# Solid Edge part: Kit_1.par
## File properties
Sűrűség: 0,000 kg/m^3
Pontosság: 0,990
Author: ahadarics
Last saved by: psaghy
Revision: 77
Username: ahadarics
Dokumentum tartalom típus: 0
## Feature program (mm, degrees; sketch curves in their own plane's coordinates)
base feature "unnamed BaseFeature 1"
sketch for "Furat_1" plane through (0, 0, 39) normal (0, 0, 1) x-axis (0, -1, 0)
  hole centre (-23.25, 23.25) bore radius 3.3235
hole "Furat_1" nominal diameter 8 finite  VBottomAngle = 118 deg; ThreadDepth = 16 mm
sketch for "unnamed Hole 1" plane through (0, 0, 39) normal (0, 0, 1) x-axis (0, -1, 0)
  hole centre (-23.25, -23.25) bore radius 3.3235
hole "unnamed Hole 1" finite
sketch for "unnamed Hole 2" plane through (0, 0, 39) normal (0, 0, 1) x-axis (0, -1, 0)
  hole centre (23.25, -23.25) bore radius 3.3235
hole "unnamed Hole 2" finite
sketch for "unnamed Hole 3" plane through (0, 0, 39) normal (0, 0, 1) x-axis (0, -1, 0)
  hole centre (23.25, 23.25) bore radius 3.3235
hole "unnamed Hole 3" finite
pattern "unnamed Pattern 1" of "Furat_1", "unnamed Hole 1", "unnamed Hole 2", "unnamed Hole 3"
sketch for "Furat_5" plane through (32.5, 0.0003, 21.2488) normal (1, 0, 0) x-axis (0, 0, -1)
hole "Furat_5" diameter 13.157 finite  ThreadDepth = 10 mm
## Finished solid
Body 1: solid body, 446 faces, 1036 edges, 651 vertices, 7 internal voids.
  Faces by surface: plane 155, cylinder 135, torus 52, cone 51, sphere 23, spline 21, swept 9
  Edges by curve: line 368, circle 356, curve on surface 286, spline 26
Bounding box of the edges (mm; curved faces can reach further): 65.000 x 65.000 x 56.500, from (-32.5, -32.5, 8) to (32.5002, 32.5, 64.5).
Cylindrical faces by radius (mm): R0.3125 x1, R0.3838 x1, R0.4089 x1, R0.4253 x1, R0.4408 x1, R0.5 x8, R0.5003 x1, R0.5483 x1, R0.5961 x1, R0.615 x1, R0.6311 x1, R0.6362 x1, R0.652 x1, R0.6792 x1, R0.73 x1, R0.7378 x1, R0.7396 x1, R0.9114 x1, R1 x20, R1.0004 x7, R1.001 x6, R1.0014 x8, R1.0015 x1, R1.0026 x1, R1.0394 x1, R1.0539 x1, R1.0734 x1, R1.0987 x1, R1.1871 x1, R1.2561 x1, R1.2722 x2, R1.3621 x1, R1.3711 x1, R1.4 x1, R1.7143 x1, R3.3235 x8, R4 x4, R4.15 x4, R4.5 x1, R5 x2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
Conical faces (half-angle, radius in mm at the cone's reference point): 0.5 deg R18.5 x4, 0.5 deg R22.25 x4, 1.6538 deg R11.75 x1, 3.5477 deg R12.7454 x1, 5.762 deg R10.4 x1, 11.1239 deg R10.0056 x1, 15 deg R18.5156 x1, 15.3654 deg R10.7214 x1, 19.3654 deg R11.1921 x1, 25.0169 deg R14.31 x1, 30 deg R5.1443 x1, 30 deg R11.8557 x2, 30 deg R12.1443 x1, 30 deg R19.5 x1, 31.4296 deg R28.625 x4, 45 deg R2.75 x1, 45 deg R2.825 x1, 45 deg R4.3 x8, 45 deg R6.35 x8, 45 deg R6.72 x1, 45 deg R10.15 x2, 45 deg R15.25 x1, 59 deg R3.3235 x4
Toroidal faces (ring radius, tube radius in mm): R0.4909 r0.5044 x1, R0.5094 r0.5004 x1, R0.8674 r0.5067 x1, R1.4976 r0.5003 x6, R4.3 r0.3 x4, R4.7 r0.3 x1, R6.45 r0.2 x4, R7.15 r0.5 x4, R9.5 r0.5 x1, R9.75 r0.5 x2, R10.3 r0.3 x1, R10.3085 r0.3 x1, R11.4279 r0.25 x1, R12.2464 r0.5 x1, R13.9897 r0.5062 x1, R14.8 r0.2 x1, R17 r2 x1, R17.6163 r0.5 x1, R19.4739 r1 x1, R19.4913 r1 x3, R20.5 r0.5 x1, R21.2587 r1 x3, R21.2761 r1 x1, R27.25 r1 x3, R31.75 r1 x6, R33.3108 r1 x1
Spherical faces by radius (mm): R0.5 x1, R1 x22
Planar faces by outward normal: +x 24, +y 9, +z 36, -x 5, -y 8, -z 24, oblique 49
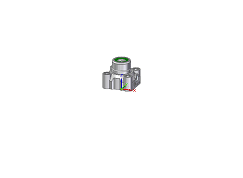
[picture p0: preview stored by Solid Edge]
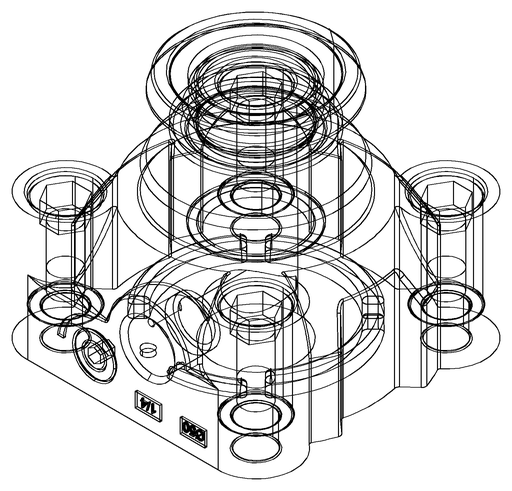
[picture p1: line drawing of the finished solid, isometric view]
